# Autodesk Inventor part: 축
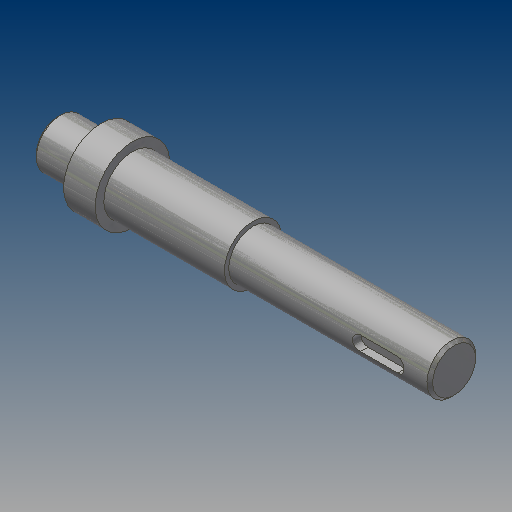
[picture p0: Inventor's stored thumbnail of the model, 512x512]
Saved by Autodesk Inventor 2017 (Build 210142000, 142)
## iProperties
Created: 2015-09
Part Number: 축
Material: 강철, 연강
Document SubType Name: Modeling
Designer: mduedu
Density: 7.86 g/cm^3
Mass: 263.424 g
Surface Area: 86.4309 cm^2
Volume: 33.5145 cm^3
Appearance: 강철
Author: mduedu
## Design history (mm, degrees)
sketch "스케치1"
  geometry: L1 (-69, 0)-(69, 0); L2 (-69, 0)-(-69, 8.5); L3 (-69, 8.5)-(-54, 8.5); L4 (-54, 8.5)-(-54, 13); L5 (-54, 13)-(-43, 13); L6 (-43, 13)-(-43, 10); L7 (-43, 10)-(-1, 10); L8 (-1, 10)-(-1, 8.5); L9 (-1, 8.5)-(69, 8.5); L10 (69, 8.5)-(69, 0); 2 further points
  constraints: 20 end point, 5 parallel, 2 horizontal, 2 perpendicular, 1 coincident, 1 midpoint, 1 vertical
  dimensions: "d0" = 138 distance of L1.start L1.end; "d2" = 11 distance of L4.end L5.end; "d3" = 42 distance of L6.end L7.end; "d4" = 70 distance of L8.end L9.end; "d5" = 17 diameter of L3 L1; "d6" = 17 diameter of L9 L1; "d7" = 20 diameter of L7 L1; "d8" = 26 diameter of L5 L1
revolve "회전1" sketch "스케치1" stored, may be unused: angle "d9" = 90 deg
node "작업 평면1"
sketch "스케치2"
  geometry: L1 (10.5, 2.5)-(23.5, 2.5); L2 (23.5, -2.5)-(10.5, -2.5); L3 (10.5, 2.5)-(23.5, -2.5); L4 (23.5, 2.5)-(10.5, -2.5); L5 (35, -8.5)-(35, 8.5) reference; A1 r 2.5 centre (10.5, 0) between (10.5, 2.5) and (10.5, -2.5); A2 r 2.5 centre (23.5, 0) between (23.5, -2.5) and (23.5, 2.5); 2 further points
  constraints: 8 end point, 4 point on circle, 4 tangent, 2 centre point, 2 midpoint, 1 horizontal, 1 horizontal alignment, 1 parallel
  dimensions: "d10" = 18 dimension on A2 A1; "d12" = 9 distance edge to line of A2 L5; "d13" = 5 distance between parallel lines of L2 L1
extrude "돌출1" cut sketch "스케치2" distance "d14" = 3; taper "d15" = 0 deg
node "작업 평면2"
sketch "스케치4"
  geometry: L1 (7, -3)-(-9, -3); L2 (-9, 3)-(7, 3); L3 (-21, 10)-(-21, -10) reference; A1 r 3 centre (-9, 0) between (-9, 3) and (-9, -3); A2 r 3 centre (7, 0) between (7, -3) and (7, 3); 1 further point
  constraints: 4 end point, 4 point on circle, 4 tangent, 2 centre point, 1 horizontal, 1 horizontal alignment, 1 parallel
  dimensions: "d16" = 22 dimension on A1 A2; "d18" = 6 distance between parallel lines of L2 L1; "d19" = 9 distance edge to line of A1 L3
extrude "돌출2" cut sketch "스케치4" distance "d20" = 3.5; taper "d21" = 0 deg
sketch "스케치5"
  geometry: L1 (-1, 8.5)-(69, 8.5) reference; L2 (-1, -8.5)-(69, -8.5) reference; L3 (42, 8.5)-(42, -8.5); L4 (42, -6.5)-(40, -8.5); L5 (42, -8.5)-(40, -8.5); L6 (42, -8.5)-(42, -6.5); L7 (-1, -10)-(-1, 10) reference; 1 further point
  constraints: 8 end point, 4 point on line, 1 collinear, 1 perpendicular
  dimensions: "d22" = 4 diameter of L4.end L3; "d24" = 45 deg angle of L3 L4; "d26" = 43 distance between parallel lines of L3 L7
revolve "회전2" sketch "스케치5" stored, may be unused: angle "d27" = 90 deg
chamfer "모따기1" distance "d28" = 1; stored, may be unused: second distance "d29" = 2, angle "d30" = 45 deg
sketch "스케치6"
  geometry: L1 (42, -6.5)-(40, -8.5) reference; L2 (42, -6.5)-(44, -8.5) reference; 2 further points
  constraints: 1 coincident
node "솔리드1"
